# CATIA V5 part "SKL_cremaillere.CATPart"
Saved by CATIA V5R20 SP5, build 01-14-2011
Part number: SKL_bati
Publications: "Point.1", "Point.3", "Droite.1", "Point.5", "Point.7", "Point.9", "Droite.2", "Plan.1", "Droite.3", "Droite.4"
Bounding box of the stored display mesh (mm): x -32 to 20, y 0 to 139.3, z -10 to 10
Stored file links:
  F:\Catia_finish\SKL_cremaillere.CATPart
  F:\Catia_finish\ASS_SKL.CATProduct
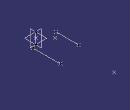
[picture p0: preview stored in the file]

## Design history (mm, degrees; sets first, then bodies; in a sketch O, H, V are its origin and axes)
Set1
  Point1 to Point5: linked copy from another document
  Plane1: linked copy from another document
  Point6: linked copy from another document
  Point7: linked copy from another document
Set2
  Point8: (0, 0, 0), relative to Point1
  Point9: (0, 0, 0), relative to Point2
  Line1: type PtPt, FirstPoint Point1, SecondPoint Point2
  Point10: (0, 0, 0), relative to Point3
  Point11: (0, 0, 0), relative to Point4
  Point12: (0, 0, 0), relative to Point5
  Line2: type PtPt, FirstPoint Point5, SecondPoint Point4
  Plane2: type Offset, RefPlane Plane1, Offset 0
  Line3: type Normal, RefPoint Point3, RefSkin Plane2, Start -10, End 10
  Line4: type PtPt, FirstPoint Point6, SecondPoint Point7
Body1 (main body)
